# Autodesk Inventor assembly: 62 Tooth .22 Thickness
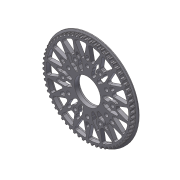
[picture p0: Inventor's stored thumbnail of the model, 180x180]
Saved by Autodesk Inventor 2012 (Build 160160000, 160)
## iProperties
Created: 2012-01
Part Number: 62 Tooth .22 Thickness
Document SubType Name: Assembly
Designer: Alex
Author: Alex
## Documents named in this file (3)
- C:\Users\Owner\Documents\Robotics\Mechanical Design\Parts\pulley\HTD\9mm\Double Flange\62 Tooth\62 Tooth .22 Thickness.iam
- C:\Users\Owner\Documents\Robotics\Mechanical Design\Parts\pulley\HTD\9mm\Double Flange\62 Tooth\HTD 5mm 62 Tooth rev001 step 2.ipt
- C:\Users\Owner\Documents\Robotics\Mechanical Design\Parts\pulley\HTD\9mm\Double Flange\62 Tooth\HTD 5mm 62 Tooth Flange_rev001.ipt
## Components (2 placed, 2 different names)
1. HTD 5mm 62 Tooth rev001 step 2:1 — Mate:1, Mate:2, Flush:1
2. HTD 5mm 62 Tooth Flange_rev001:1 — Mate:1, Mate:2
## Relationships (3: Mate 2, Flush 1)
- Mate:1: HTD 5mm 62 Tooth rev001 step 2:1 ↔ HTD 5mm 62 Tooth Flange_rev001:1
- Mate:2: HTD 5mm 62 Tooth rev001 step 2:1 ↔ HTD 5mm 62 Tooth Flange_rev001:1
- Flush:1: HTD 5mm 62 Tooth rev001 step 2:1
